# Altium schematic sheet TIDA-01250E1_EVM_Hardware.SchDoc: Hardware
size 431 x 279 mm; Date: Not shown in title block; ApprovedBy: Not shown in title block; CheckedBy: Not shown in title block; Author: Not shown in title block; CompanyName: Not shown in title block; DrawnBy: AW; Engineer: Not shown in title block; Organization: Not shown in title block; Address1: Not shown in title block; Address2: Not shown in title block; Address3: Not shown in title block; Address4: Not shown in title block; DocumentNumber: 3; Revision: Use project parameter SCH_Rev; SheetNumber: 3; SheetTotal: 3; PageSetup: Record=PageOptions¦CenterHorizontal=True¦CenterVertical=True¦PrintScale=1.00¦XCorrection=1.00¦YCorrection=1.00¦PrintKind=0¦BorderSize=5000000¦LeftOffset=0¦BottomOffset=0¦Orientation=2¦PaperLength=1000¦PaperWidth=1000¦Scale=100¦PaperSource=15¦PrintQuality=600¦MediaType=1¦DitherType=10¦PaperKind=Letter¦PrintScaleMode=1
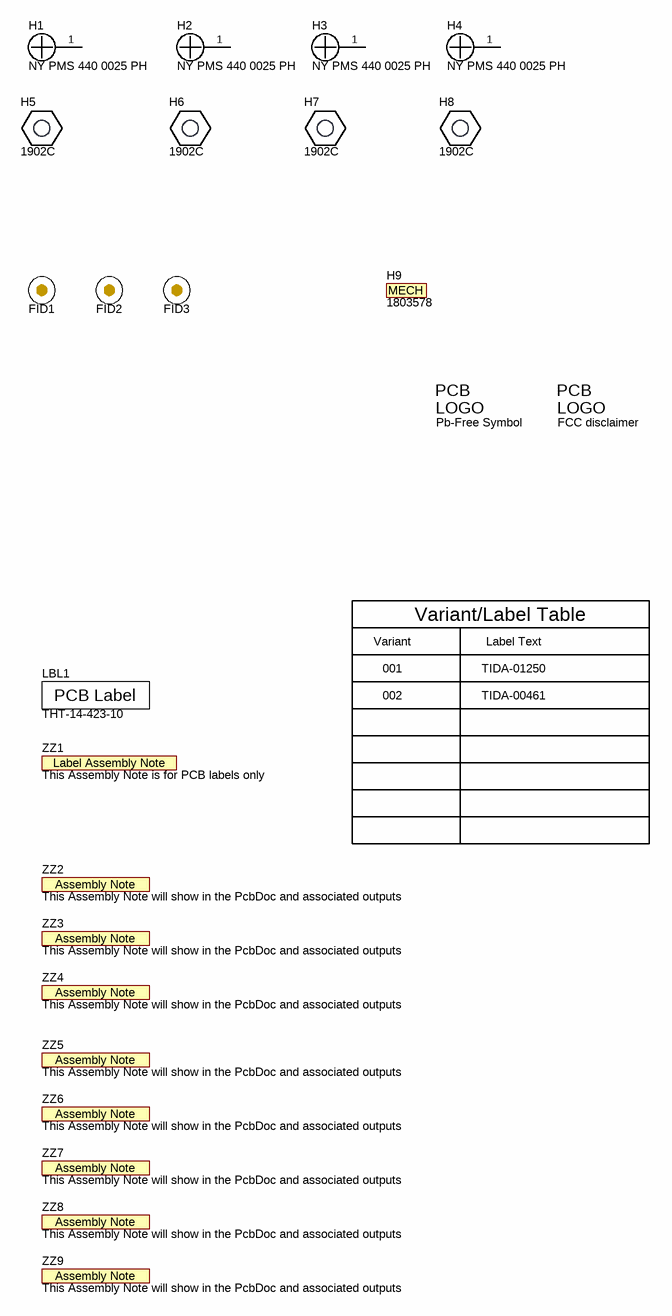
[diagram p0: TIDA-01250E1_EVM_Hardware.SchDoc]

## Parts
FID1  Fiducial  [Fiducial10-20]  (value not drawn)
FID2  Fiducial  [Fiducial10-20]  (value not drawn)
FID3  Fiducial  [Fiducial10-20]  (value not drawn)
H1  NY PMS 440 0025 PH  [NY PMS 440 0025 PH]
H2  NY PMS 440 0025 PH  [NY PMS 440 0025 PH]
H3  NY PMS 440 0025 PH  [NY PMS 440 0025 PH]
H4  NY PMS 440 0025 PH  [NY PMS 440 0025 PH]
H5  1902C  [Keystone_1902C]
H6  1902C  [Keystone_1902C]
H7  1902C  [Keystone_1902C]
H8  1902C  [Keystone_1902C]
H9  1803578  (mechanical)
LBL1  THT-14-423-10  [Label_650x200]
Logo2  Pb-Free Symbol  [Pb-Free_Overlay_Small]  (no BOM)
Logo3  FCC disclaimer  [FCC_disclaimer]  (no BOM)
ZZ1  This Assembly Note is for PCB labels only  [AssemblyNoteLabel]  (no BOM)
ZZ2  This Assembly Note will show in the PcbDoc and associated outputs  [AssemblyNote]  (no BOM)
ZZ3  This Assembly Note will show in the PcbDoc and associated outputs  [AssemblyNote]  (no BOM)
ZZ4  This Assembly Note will show in the PcbDoc and associated outputs  [AssemblyNote]  (no BOM)
ZZ5  This Assembly Note will show in the PcbDoc and associated outputs  [AssemblyNote]  (no BOM)
ZZ6  This Assembly Note will show in the PcbDoc and associated outputs  [AssemblyNote]  (no BOM)
ZZ7  This Assembly Note will show in the PcbDoc and associated outputs  [AssemblyNote]  (no BOM)
ZZ8  This Assembly Note will show in the PcbDoc and associated outputs  [AssemblyNote]  (no BOM)
ZZ9  This Assembly Note will show in the PcbDoc and associated outputs  [AssemblyNote]  (no BOM)

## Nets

Not connected (* = marked no-connect by the designer): H1 1; H2 1; H3 1; H4 1

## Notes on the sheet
- Variant
- Variant/Label Table
- Label Text
- 001
- 002
- TIDA-01250
- TIDA-00461

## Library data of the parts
FID1-FID3 = Fiducial: Fiducial mark.  There is nothing to buy or mount.; SymbolCreator: codlsc
H1-H4 = CMP-0003617-1: Machine Screw, Round, #4-40 x 1/4, Nylon, Philips panhead; Manufacturer: B&F Fastener Supply; CompType: Hardware
H5-H8 = CMP-0003610-1: Standoff, Hex, 0.5"L #4-40 Nylon; Manufacturer: Keystone; CompType: Hardware
H9 = CMP-0003847-1: Terminal Block Plug, 3.81mm, 2x1, Green; Manufacturer: Phoenix Contact; CompType: TERM BLOCK
LBL1 = CMP-0003625-1: Thermal Transfer Printable Labels, 0.650" W x 0.200" H - 10,000 per roll; Manufacturer: Brady; Note: Size: 0.65" x 0.20 "
Logo2 = Pb-Free: SymbolCreator: a0412235
Logo3 = FCC_disclaimer: SymbolCreator: a0412235
ZZ1 = AssemblyNoteLabel: SymbolCreator: a0412235
ZZ2-ZZ9 = AssemblyNote: SymbolCreator: codlsc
